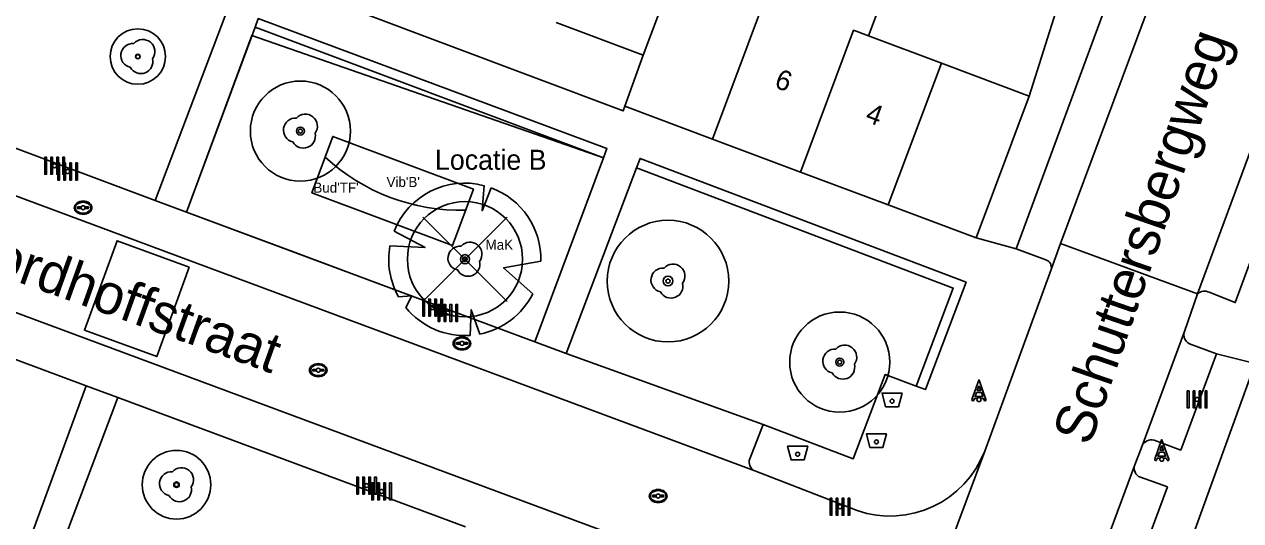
# Model space of a CAD drawing. Extents: x 192664 to 192925, y 446334 to 446521.
# Drawn here: x 192777.1 to 192837.8, y 446370.9 to 446395.7 of the extents above; entities that cross this region are included whole.
import ezdxf

# ---------------------------------------------------------------- set-up
doc = ezdxf.new("R2010")
doc.units = 0
for name, color, linetype in [('( Toegevoegd 29-11-2021 14_41_42) wegdeel vlak', 7, 'Continuous'), ('B-GV-GR-BOOM-S', 7, 'Continuous'), ('B-GV-KG-GRENS_WERKGRENS-G', 7, 'Continuous'), ('boom', 7, 'Continuous'), ('bovenleidingmast', 7, 'Continuous'), ('container', 7, 'Continuous'), ('huisnummerreeks BGT', 7, 'Continuous'), ('inspectie-   rioolput', 7, 'Continuous'), ('kant open verharding', 7, 'Continuous'), ('kant verharding', 7, 'Continuous'), ('kolk', 7, 'Continuous'), ('N-GV-GR-BEPLANTING-G', 7, 'Continuous'), ('N-GV-GR-BOOM-S', 7, 'Continuous'), ('pand op maaiveld vlak', 7, 'Continuous'), ('straatnaam', 7, 'Continuous'), ('TEKST', 7, 'Continuous'), ('verkeerseiland - berm', 7, 'Continuous')]:
    doc.layers.add(name, color=color, linetype=linetype)

msp = doc.modelspace()

# ---------------------------------------------------------------- linework, layer by layer
at = {"layer": '( Toegevoegd 29-11-2021 14_41_42) wegdeel vlak'}
for p, q in [((192826.627, 446384.5), (192824.633, 446385.044)), ((192813.567, 446373.412), (192818.683, 446371.433))]:
    msp.add_line(p, q, dxfattribs=at)
for points in [[(192807.071, 446391.618), (192806.989, 446391.38), (192789.199, 446398.084), (192788.212, 446398.449), (192770.35, 446405.075), (192770.467, 446405.283)], [(192806.008, 446389.049), (192806.18, 446389.51), (192788.76, 446395.99), (192788.604, 446395.572)], [(192821.627, 446377.648), (192822.094, 446377.471), (192824.128, 446382.832), (192807.836, 446389.015), (192807.659, 446388.548)]]:
    msp.add_lwpolyline(points, dxfattribs=at)
at = {"layer": 'B-GV-GR-BOOM-S'}
for p, q in [((192801.192, 446386.083), (192796.987, 446381.877)), ((192801.192, 446381.877), (192796.987, 446386.083))]:
    msp.add_line(p, q, dxfattribs=at)
for centre, radius in [((192782.744, 446394.098), 1.384), ((192782.744, 446394.098), 0.111), ((192790.866, 446390.376), 2.5), ((192790.866, 446390.376), 0.2), ((192799.089, 446383.98), 2.877), ((192809.234, 446382.89), 3.036), ((192799.089, 446383.98), 0.23), ((192809.234, 446382.89), 0.243), ((192817.815, 446378.845), 2.5), ((192817.815, 446378.845), 0.2), ((192784.676, 446372.725), 1.713), ((192784.676, 446372.725), 0.137)]:
    msp.add_circle(centre, radius, dxfattribs=at)
at = {"layer": 'B-GV-KG-GRENS_WERKGRENS-G'}
msp.add_lwpolyline([(192788.443, 446395.14), (192806.008, 446389.049), (192802.587, 446379.853), (192794.566, 446382.838), (192790.602, 446384.314), (192785.169, 446386.336)], close=True, dxfattribs=at)
at = {"layer": 'boom'}
for centre in [(192782.744, 446394.098), (192790.866, 446390.376), (192799.091, 446383.98), (192809.234, 446382.89), (192817.815, 446378.845), (192784.676, 446372.725)]:
    msp.add_circle(centre, 0.1, dxfattribs=at)
for centre, radius, start, end in [((192782.494, 446394.148), 0.6, 85.13702, 257.75442), ((192782.994, 446394.348), 0.6, 323.54458, 138.4658), ((192782.744, 446394.098), 0.1, 0, 180), ((192782.744, 446394.098), 0.1, 180, 0), ((192782.894, 446393.848), 0.6, 208.50578, 13.83556), ((192790.616, 446390.426), 0.6, 85.13702, 257.75442), ((192791.116, 446390.626), 0.6, 323.54458, 138.4658), ((192790.866, 446390.376), 0.1, 0, 180), ((192791.016, 446390.126), 0.6, 208.50578, 13.83556), ((192790.866, 446390.376), 0.1, 180, 0), ((192798.841, 446384.03), 0.6, 85.13702, 257.75442), ((192799.341, 446384.23), 0.6, 323.54458, 138.4658), ((192799.241, 446383.73), 0.6, 208.50578, 13.83556), ((192799.091, 446383.98), 0.1, 0, 180), ((192799.091, 446383.98), 0.1, 180, 0), ((192809.484, 446383.14), 0.6, 323.54458, 138.4658), ((192808.984, 446382.94), 0.6, 85.13702, 257.75442), ((192809.384, 446382.64), 0.6, 208.50578, 13.83556), ((192809.234, 446382.89), 0.1, 0, 180), ((192809.234, 446382.89), 0.1, 180, 0), ((192817.565, 446378.895), 0.6, 85.13702, 257.75442), ((192818.065, 446379.095), 0.6, 323.54458, 138.4658), ((192817.815, 446378.845), 0.1, 0, 180), ((192817.815, 446378.845), 0.1, 180, 0), ((192817.965, 446378.595), 0.6, 208.50578, 13.83556), ((192784.426, 446372.775), 0.6, 85.13702, 257.75442), ((192784.926, 446372.975), 0.6, 323.54458, 138.4658), ((192784.676, 446372.725), 0.1, 0, 180), ((192784.826, 446372.475), 0.6, 208.50578, 13.83556), ((192784.676, 446372.725), 0.1, 180, 0)]:
    msp.add_arc(centre, radius, start, end, dxfattribs=at)
at = {"layer": 'bovenleidingmast'}
for p, q in [((192824.763, 446377.948), (192824.422, 446376.975)), ((192825.122, 446376.975), (192824.781, 446377.948)), ((192833.899, 446374.969), (192833.558, 446373.996)), ((192834.258, 446373.996), (192833.917, 446374.969))]:
    msp.add_line(p, q, dxfattribs=at)
for points in [[(192824.781, 446377.645), (192824.859, 446377.425), (192824.685, 446377.425), (192824.763, 446377.645)], [(192824.516, 446376.942), (192824.545, 446377.025), (192824.685, 446377.025)], [(192824.859, 446377.025), (192824.999, 446377.025), (192825.028, 446376.942)], [(192833.917, 446374.666), (192833.995, 446374.446), (192833.821, 446374.446), (192833.899, 446374.666)], [(192833.652, 446373.963), (192833.681, 446374.046), (192833.821, 446374.046)], [(192833.995, 446374.046), (192834.135, 446374.046), (192834.164, 446373.963)]]:
    msp.add_lwpolyline(points, dxfattribs=at)
for points in [[(192824.894, 446377.325), (192824.964, 446377.125), (192824.58, 446377.125), (192824.65, 446377.325)], [(192834.03, 446374.346), (192834.1, 446374.146), (192833.716, 446374.146), (192833.786, 446374.346)]]:
    msp.add_lwpolyline(points, close=True, dxfattribs=at)
for centre, radius, start, end in [((192824.772, 446377.945), 0.01, 19.29005, 160.70995), ((192824.772, 446377.642), 0.01, 19.29005, 160.70995), ((192824.772, 446376.975), 0.1, 0, 180), ((192824.772, 446376.975), 0.1, 30, 150), ((192824.469, 446376.958), 0.05, 160.70995, 340.70995), ((192824.772, 446376.975), 0.1, 180, 0), ((192825.075, 446376.958), 0.05, 199.29005, 19.29005), ((192833.908, 446374.966), 0.01, 19.29005, 160.70995), ((192833.908, 446374.663), 0.01, 19.29005, 160.70995), ((192833.605, 446373.979), 0.05, 160.70995, 340.70995), ((192833.908, 446373.996), 0.1, 0, 180), ((192833.908, 446373.996), 0.1, 180, 0), ((192833.908, 446373.996), 0.1, 30, 150), ((192834.211, 446373.979), 0.05, 199.29005, 19.29005)]:
    msp.add_arc(centre, radius, start, end, dxfattribs=at)
at = {"layer": 'container'}
for points in [[(192820.758, 446376.621), (192820.933, 446377.296), (192819.933, 446377.296), (192820.108, 446376.621)], [(192819.974, 446374.589), (192820.149, 446375.264), (192819.149, 446375.264), (192819.324, 446374.589)], [(192816.038, 446373.974), (192816.213, 446374.649), (192815.213, 446374.649), (192815.388, 446373.974)]]:
    msp.add_lwpolyline(points, close=True, dxfattribs=at)
for centre in [(192820.433, 446376.896), (192819.649, 446374.864), (192815.713, 446374.249)]:
    msp.add_circle(centre, 0.1, dxfattribs=at)
for centre, start, end in [((192820.433, 446376.896), 0, 180), ((192820.433, 446376.896), 180, 0), ((192819.649, 446374.864), 0, 180), ((192819.649, 446374.864), 180, 0), ((192815.713, 446374.249), 0, 180), ((192815.713, 446374.249), 180, 0)]:
    msp.add_arc(centre, 0.1, start, end, dxfattribs=at)
at = {"layer": 'inspectie-   rioolput'}
for p, q in [((192779.917, 446386.591), (192779.76, 446386.591)), ((192779.76, 446386.517), (192779.917, 446386.517)), ((192780.26, 446386.591), (192780.103, 446386.591)), ((192780.103, 446386.517), (192780.26, 446386.517)), ((192798.847, 446379.818), (192798.69, 446379.818)), ((192798.69, 446379.742), (192798.847, 446379.742)), ((192799.19, 446379.818), (192799.033, 446379.818)), ((192799.033, 446379.742), (192799.19, 446379.742)), ((192791.669, 446378.48), (192791.512, 446378.48)), ((192791.512, 446378.405), (192791.669, 446378.405)), ((192792.012, 446378.48), (192791.855, 446378.48)), ((192791.855, 446378.405), (192792.012, 446378.405)), ((192808.65, 446372.197), (192808.493, 446372.197)), ((192808.993, 446372.197), (192808.836, 446372.197)), ((192808.493, 446372.122), (192808.65, 446372.122)), ((192808.836, 446372.122), (192808.993, 446372.122))]:
    msp.add_line(p, q, dxfattribs=at)
for centre, radius, start, end in [((192779.76, 446386.554), 0.0375, 90, 270), ((192780.01, 446386.554), 0.1, 0, 180), ((192780.01, 446386.554), 0.1, 157.97569, 180), ((192780.01, 446386.554), 0.1, 180, 202.02431), ((192780.01, 446386.554), 0.1, 180, 0), ((192780.01, 446386.554), 0.1, 0, 22.02431), ((192780.01, 446386.554), 0.1, 337.97569, 0), ((192780.26, 446386.554), 0.0375, 270, 90), ((192798.69, 446379.78), 0.0375, 90, 270), ((192798.94, 446379.78), 0.1, 0, 180), ((192798.94, 446379.78), 0.1, 157.97569, 180), ((192798.94, 446379.78), 0.1, 180, 202.02431), ((192798.94, 446379.78), 0.1, 180, 0), ((192798.94, 446379.78), 0.1, 0, 22.02431), ((192798.94, 446379.78), 0.1, 337.97569, 0), ((192799.19, 446379.78), 0.0375, 270, 90), ((192791.512, 446378.442), 0.0375, 90, 270), ((192791.762, 446378.442), 0.1, 0, 180), ((192791.762, 446378.442), 0.1, 157.97569, 180), ((192791.762, 446378.442), 0.1, 180, 202.02431), ((192791.762, 446378.442), 0.1, 180, 0), ((192791.762, 446378.442), 0.1, 0, 22.02431), ((192791.762, 446378.442), 0.1, 337.97569, 0), ((192792.012, 446378.442), 0.0375, 270, 90), ((192808.493, 446372.159), 0.0375, 90, 270), ((192808.743, 446372.159), 0.1, 0, 180), ((192808.743, 446372.159), 0.1, 157.97569, 180), ((192808.743, 446372.159), 0.1, 180, 202.02431), ((192808.743, 446372.159), 0.1, 180, 0), ((192808.743, 446372.159), 0.1, 0, 22.02431), ((192808.743, 446372.159), 0.1, 337.97569, 0), ((192808.993, 446372.159), 0.0375, 270, 90)]:
    msp.add_arc(centre, radius, start, end, dxfattribs=at)
for centre, major_axis, ratio in [((192780.01, 446386.554), (-0.442, 0), 0.73911), ((192780.01, 446386.554), (-0.392, 0), 0.689655), ((192798.94, 446379.78), (-0.442, 0), 0.73911), ((192798.94, 446379.78), (-0.392, 0), 0.689655), ((192791.762, 446378.442), (-0.442, 0), 0.73911), ((192791.762, 446378.442), (-0.392, 0), 0.689655), ((192808.743, 446372.159), (-0.442, 0), 0.73911), ((192808.743, 446372.159), (-0.392, 0), 0.689655)]:
    msp.add_ellipse(centre, major_axis=major_axis, ratio=ratio, dxfattribs=at)
at = {"layer": 'kant open verharding'}
for p, q in [((192835.688, 446382.26), (192828.852, 446384.771)), ((192836.641, 446379.267), (192838.566, 446378.775)), ((192838.566, 446378.775), (192827.102, 446347.165)), ((192832.92, 446374.663), (192832.554, 446373.716)), ((192819.665, 446359.922), (192825.062, 446374.407))]:
    msp.add_line(p, q, dxfattribs=at)
for points in [[(192829.343, 446398.525), (192828.71, 446396.639), (192827.284, 446392.126)], [(192785.316, 446383.588), (192781.705, 446384.906), (192780.074, 446380.436), (192783.685, 446379.118), (192785.316, 446383.588)]]:
    msp.add_lwpolyline(points, dxfattribs=at)
at = {"layer": 'kant verharding'}
for p, q in [((192828.852, 446384.771), (192835.348, 446402.2)), ((192842.311, 446400.15), (192835.688, 446382.26)), ((192753.133, 446395.89), (192813.567, 446373.412)), ((192751.186, 446390.775), (192811.557, 446368.364)), ((192785.169, 446386.336), (192783.608, 446386.92)), ((192826.627, 446384.5), (192828.113, 446383.955)), ((192828.377, 446383.473), (192828.852, 446384.771)), ((192828.377, 446383.473), (192825.062, 446374.407)), ((192835.035, 446380.378), (192835.688, 446382.26)), ((192832.92, 446374.663), (192835.035, 446380.378)), ((192802.587, 446379.853), (192804.14, 446379.275)), ((192836.641, 446379.267), (192835.29, 446379.763)), ((192780.156, 446377.668), (192781.749, 446377.077)), ((192813.995, 446375.727), (192813.321, 446374.017)), ((192823.215, 446348.469), (192832.554, 446373.716))]:
    msp.add_line(p, q, dxfattribs=at)
for points in [[(192834.695, 446401.945), (192833.274, 446402.505), (192826.627, 446384.5)], [(192842.625, 446399.67), (192843.965, 446399.128), (192837.574, 446381.816), (192836.276, 446382.332)], [(192833.525, 446374.955), (192834.855, 446374.452), (192836.641, 446379.267)], [(192825.128, 446348.244), (192834.188, 446372.616), (192832.836, 446373.098)]]:
    msp.add_lwpolyline(points, dxfattribs=at)
for centre, radius, start, end in [((192827.987, 446383.573), 0.403, 345.68825, 71.73236), ((192836.037, 446381.843), 0.544, 63.99711, 129.965), ((192835.515, 446380.217), 0.506, 161.39229, 243.64884), ((192833.395, 446374.452), 0.519, 75.47321, 156.05485), ((192813.766, 446373.846), 0.477, 158.93612, 245.31834), ((192820.325, 446376.24), 5.079, 251.14064, 338.85086), ((192833.017, 446373.554), 0.491, 160.74669, 248.30876)]:
    msp.add_arc(centre, radius, start, end, dxfattribs=at)
at = {"layer": 'kolk'}
for points in [[(192778.181, 446388.645), (192778.181, 446389.07), (192778.096, 446389.07), (192778.096, 446388.645), (192778.096, 446388.22), (192778.181, 446388.22)], [(192778.479, 446388.645), (192778.479, 446389.07), (192778.394, 446389.07), (192778.394, 446388.645), (192778.394, 446388.22), (192778.479, 446388.22)], [(192778.776, 446388.645), (192778.776, 446389.07), (192778.691, 446389.07), (192778.691, 446388.645), (192778.691, 446388.22), (192778.776, 446388.22)], [(192778.831, 446388.36), (192778.831, 446388.785), (192778.746, 446388.785), (192778.746, 446388.36), (192778.746, 446387.935), (192778.831, 446387.935)], [(192779.074, 446388.645), (192779.074, 446389.07), (192778.989, 446389.07), (192778.989, 446388.645), (192778.989, 446388.22), (192779.074, 446388.22)], [(192779.129, 446388.36), (192779.129, 446388.785), (192779.044, 446388.785), (192779.044, 446388.36), (192779.044, 446387.935), (192779.129, 446387.935)], [(192779.426, 446388.36), (192779.426, 446388.785), (192779.341, 446388.785), (192779.341, 446388.36), (192779.341, 446387.935), (192779.426, 446387.935)], [(192779.724, 446388.36), (192779.724, 446388.785), (192779.639, 446388.785), (192779.639, 446388.36), (192779.639, 446387.935), (192779.724, 446387.935)], [(192797.069, 446381.567), (192797.069, 446381.992), (192796.984, 446381.992), (192796.984, 446381.567), (192796.984, 446381.142), (192797.069, 446381.142)], [(192797.367, 446381.567), (192797.367, 446381.992), (192797.282, 446381.992), (192797.282, 446381.567), (192797.282, 446381.142), (192797.367, 446381.142)], [(192797.664, 446381.567), (192797.664, 446381.992), (192797.579, 446381.992), (192797.579, 446381.567), (192797.579, 446381.142), (192797.664, 446381.142)], [(192797.962, 446381.567), (192797.962, 446381.992), (192797.877, 446381.992), (192797.877, 446381.567), (192797.877, 446381.142), (192797.962, 446381.142)], [(192797.83, 446381.301), (192797.83, 446381.726), (192797.745, 446381.726), (192797.745, 446381.301), (192797.745, 446380.876), (192797.83, 446380.876)], [(192798.128, 446381.301), (192798.128, 446381.726), (192798.043, 446381.726), (192798.043, 446381.301), (192798.043, 446380.876), (192798.128, 446380.876)], [(192798.425, 446381.301), (192798.425, 446381.726), (192798.34, 446381.726), (192798.34, 446381.301), (192798.34, 446380.876), (192798.425, 446380.876)], [(192798.723, 446381.301), (192798.723, 446381.726), (192798.638, 446381.726), (192798.638, 446381.301), (192798.638, 446380.876), (192798.723, 446380.876)], [(192835.267, 446376.982), (192835.267, 446377.407), (192835.182, 446377.407), (192835.182, 446376.982), (192835.182, 446376.557), (192835.267, 446376.557)], [(192835.565, 446376.982), (192835.565, 446377.407), (192835.48, 446377.407), (192835.48, 446376.982), (192835.48, 446376.557), (192835.565, 446376.557)], [(192835.862, 446376.982), (192835.862, 446377.407), (192835.777, 446377.407), (192835.777, 446376.982), (192835.777, 446376.557), (192835.862, 446376.557)], [(192836.16, 446376.982), (192836.16, 446377.407), (192836.075, 446377.407), (192836.075, 446376.982), (192836.075, 446376.557), (192836.16, 446376.557)], [(192793.768, 446372.686), (192793.768, 446373.111), (192793.683, 446373.111), (192793.683, 446372.686), (192793.683, 446372.261), (192793.768, 446372.261)], [(192794.066, 446372.686), (192794.066, 446373.111), (192793.981, 446373.111), (192793.981, 446372.686), (192793.981, 446372.261), (192794.066, 446372.261)], [(192794.363, 446372.686), (192794.363, 446373.111), (192794.278, 446373.111), (192794.278, 446372.686), (192794.278, 446372.261), (192794.363, 446372.261)], [(192794.518, 446372.391), (192794.518, 446372.816), (192794.433, 446372.816), (192794.433, 446372.391), (192794.433, 446371.966), (192794.518, 446371.966)], [(192794.661, 446372.686), (192794.661, 446373.111), (192794.576, 446373.111), (192794.576, 446372.686), (192794.576, 446372.261), (192794.661, 446372.261)], [(192794.816, 446372.391), (192794.816, 446372.816), (192794.731, 446372.816), (192794.731, 446372.391), (192794.731, 446371.966), (192794.816, 446371.966)], [(192795.113, 446372.391), (192795.113, 446372.816), (192795.028, 446372.816), (192795.028, 446372.391), (192795.028, 446371.966), (192795.113, 446371.966)], [(192795.411, 446372.391), (192795.411, 446372.816), (192795.326, 446372.816), (192795.326, 446372.391), (192795.326, 446371.966), (192795.411, 446371.966)], [(192817.426, 446371.628), (192817.426, 446372.053), (192817.341, 446372.053), (192817.341, 446371.628), (192817.341, 446371.203), (192817.426, 446371.203)], [(192817.724, 446371.628), (192817.724, 446372.053), (192817.639, 446372.053), (192817.639, 446371.628), (192817.639, 446371.203), (192817.724, 446371.203)], [(192818.021, 446371.628), (192818.021, 446372.053), (192817.936, 446372.053), (192817.936, 446371.628), (192817.936, 446371.203), (192818.021, 446371.203)], [(192818.319, 446371.628), (192818.319, 446372.053), (192818.234, 446372.053), (192818.234, 446371.628), (192818.234, 446371.203), (192818.319, 446371.203)]]:
    msp.add_lwpolyline(points, close=True, dxfattribs=at)
for centre, start, end in [((192778.585, 446388.645), 0, 180), ((192778.585, 446388.645), 180, 0), ((192779.235, 446388.36), 0, 180), ((192779.235, 446388.36), 180, 0), ((192797.473, 446381.567), 0, 180), ((192797.473, 446381.567), 180, 0), ((192798.234, 446381.301), 0, 180), ((192798.234, 446381.301), 180, 0), ((192835.671, 446376.982), 0, 180), ((192835.671, 446376.982), 180, 0), ((192794.172, 446372.686), 0, 180), ((192794.172, 446372.686), 180, 0), ((192794.922, 446372.391), 0, 180), ((192794.922, 446372.391), 180, 0), ((192817.83, 446371.628), 0, 180), ((192817.83, 446371.628), 180, 0)]:
    msp.add_arc(centre, 0.1, start, end, dxfattribs=at)
at = {"layer": 'N-GV-GR-BEPLANTING-G'}
msp.add_line((192792.487, 446390.112), (192799.51, 446387.48), dxfattribs=at)
msp.add_lwpolyline([(192798.464, 446384.668), (192791.442, 446387.3), (192792.487, 446390.112), (192799.51, 446387.48)], close=True, dxfattribs=at)
msp.add_lwpolyline([(192792.487, 446390.112), (192791.442, 446387.3), (192798.464, 446384.668), (192799.51, 446387.48)], dxfattribs=at)
msp.add_arc((192798.891, 446396.422), 10, 227.24832, 271.29848, dxfattribs=at)
at = {"layer": 'N-GV-GR-BOOM-S'}
for points in [[(192800.056, 446387.653), (192799.944, 446386.397), (192800.391, 446387.547)], [(192795.339, 446384.651), (192797.096, 446384.568), (192795.548, 446385.381)], [(192802.887, 446383.876), (192801.02, 446383.558), (192802.48, 446382.259)], [(192796.138, 446381.566), (192796.437, 446382.146), (192795.77, 446382.105)], [(192799.833, 446380.244), (192799.4, 446381.457), (192799.356, 446380.179)]]:
    msp.add_lwpolyline(points, dxfattribs=at)
msp.add_circle((192799.083, 446383.974), 0.113, dxfattribs=at)
for start, end in [(75.18441, 158.29895), (358.52408, 69.90661), (169.74905, 209.43023), (281.36007, 333.20465), (219.26669, 274.10684)]:
    msp.add_arc((192799.083, 446383.974), 3.805, start, end, dxfattribs=at)
at = {"layer": 'pand op maaiveld vlak'}
for p, q in [((192809.693, 446398.714), (192807.995, 446394.168)), ((192819.25, 446395.133), (192820.25, 446397.804)), ((192811.461, 446389.974), (192814.113, 446397.059)), ((192803.639, 446395.798), (192807.995, 446394.168)), ((192819.25, 446395.133), (192822.893, 446393.769)), ((192807.071, 446391.618), (192807.995, 446394.168)), ((192820.243, 446386.688), (192822.893, 446393.769)), ((192827.284, 446392.126), (192822.893, 446393.769)), ((192807.071, 446391.618), (192811.461, 446389.974)), ((192827.284, 446392.126), (192824.633, 446385.044)), ((192811.461, 446389.974), (192815.852, 446388.331)), ((192815.852, 446388.331), (192820.243, 446386.688)), ((192824.633, 446385.044), (192820.243, 446386.688))]:
    msp.add_line(p, q, dxfattribs=at)
msp.add_lwpolyline([(192819.25, 446395.133), (192818.503, 446395.413), (192815.852, 446388.331)], dxfattribs=at)
at = {"layer": 'verkeerseiland - berm'}
for p, q in [((192787.1, 446396.135), (192783.608, 446386.92)), ((192788.604, 446395.572), (192785.169, 446386.336)), ((192806.008, 446389.049), (192788.604, 446395.572)), ((192783.608, 446386.92), (192766.521, 446393.307)), ((192806.008, 446389.049), (192802.587, 446379.853)), ((192807.659, 446388.548), (192804.14, 446379.275)), ((192785.169, 446386.336), (192802.587, 446379.853)), ((192762.674, 446384.166), (192780.156, 446377.668)), ((192813.995, 446375.727), (192804.14, 446379.275)), ((192780.156, 446377.668), (192776.611, 446368.02)), ((192781.749, 446377.077), (192778.115, 446367.463)), ((192781.749, 446377.077), (192799.123, 446370.623))]:
    msp.add_line(p, q, dxfattribs=at)
for points in [[(192821.627, 446377.648), (192823.483, 446382.542), (192807.659, 446388.548)], [(192813.995, 446375.727), (192818.489, 446374.022), (192820.087, 446378.233), (192821.627, 446377.648)]]:
    msp.add_lwpolyline(points, dxfattribs=at)

# ---------------------------------------------------------------- texts
at = {"layer": 'huisnummerreeks BGT'}
for s, p in [('6', (192814.497, 446392.574)), ('4', (192819.036, 446390.877))]:
    msp.add_text(s, height=1, rotation=339.5, dxfattribs=at).set_placement(p)
at = {"layer": 'straatnaam'}
for s, rotation, p in [('Schuttersbergweg', 71, (192830.311, 446374.61)), ('Fokke Noordhoffstraat', 340.2, (192764.533, 446387.236))]:
    msp.add_text(s, height=2, rotation=rotation, dxfattribs=at).set_placement(p)
at = {"layer": 'TEKST'}
for s, height, p in [('Locatie B', 1, (192797.59, 446388.446)), ("Vib'B'", 0.5, (192795.171, 446387.586)), ("Bud'TF'", 0.5, (192791.514, 446387.304)), ('MaK', 0.5, (192800.119, 446384.454))]:
    msp.add_text(s, height=height, dxfattribs=at).set_placement(p)

doc.saveas('drawing.dxf')
